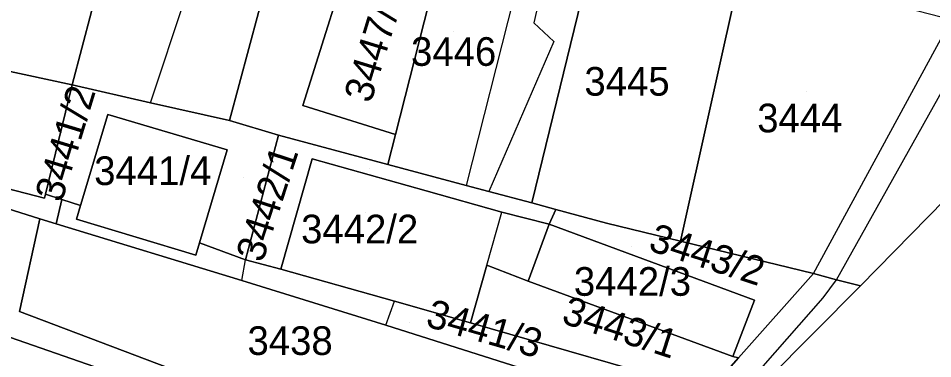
# Model space of a CAD drawing. Extents: x -262657 to -261595, y -1238015 to -1237156.
# Drawn here: x -262129.4 to -262065.5, y -1237560.4 to -1237536.7 of the extents above; entities that cross this region are included whole.
import ezdxf

# ---------------------------------------------------------------- set-up
doc = ezdxf.new("R2010")
doc.units = 0
for name, color, linetype in [('body_kn', 7, 'Continuous'), ('kladpar_druhypozemkov', 7, 'Continuous'), ('kladpar_hranice', 7, 'Continuous'), ('kladpar_parcelnecisla', 7, 'Continuous'), ('kladpar_plochy', 7, 'Continuous'), ('zappar_hrandruhpozemk', 7, 'Continuous')]:
    doc.layers.add(name, color=color, linetype=linetype)

msp = doc.modelspace()

# ---------------------------------------------------------------- linework, layer by layer
at = {"layer": 'body_kn'}
for p, q in [((-262093.38, -1237536.98), (-262093.38, -1237536.98)), ((-262091.97, -1237538.29), (-262091.97, -1237538.29)), ((-262125.61, -1237541.31), (-262125.61, -1237541.31)), ((-262120.15, -1237542.57), (-262120.15, -1237542.57)), ((-262120.15, -1237542.57), (-262120.15, -1237542.57)), ((-262109.51, -1237542.75), (-262109.51, -1237542.75)), ((-262123.13, -1237543.37), (-262123.13, -1237543.37)), ((-262114.63, -1237543.8), (-262114.63, -1237543.8)), ((-262103.04, -1237544.78), (-262103.04, -1237544.78)), ((-262111.21, -1237544.82), (-262111.21, -1237544.82)), ((-262111.21, -1237544.82), (-262111.21, -1237544.82)), ((-262114.78, -1237545.85), (-262114.78, -1237545.85)), ((-262108.85, -1237546.48), (-262108.85, -1237546.48)), ((-262108.85, -1237546.48), (-262108.85, -1237546.48)), ((-262103.57, -1237546.86), (-262103.57, -1237546.86)), ((-262098.1, -1237548.32), (-262098.1, -1237548.32)), ((-262127.54, -1237549.21), (-262127.54, -1237549.21)), ((-262127.48, -1237548.94), (-262127.48, -1237548.94)), ((-262100.9, -1237548.71), (-262100.9, -1237548.71)), ((-262096.53, -1237548.74), (-262096.53, -1237548.74)), ((-262126.34, -1237549.3), (-262126.34, -1237549.3)), ((-262126.34, -1237549.3), (-262126.34, -1237549.3)), ((-262125.02, -1237549.72), (-262125.02, -1237549.72)), ((-262093.52, -1237549.55), (-262093.52, -1237549.55)), ((-262095.62, -1237550.19), (-262095.62, -1237550.19)), ((-262091.83, -1237550.01), (-262091.83, -1237550.01)), ((-262127.87, -1237550.65), (-262127.87, -1237550.65)), ((-262126.73, -1237551), (-262126.73, -1237551)), ((-262125.3, -1237550.68), (-262125.3, -1237550.68)), ((-262092.31, -1237551.03), (-262092.31, -1237551.03)), ((-262092.31, -1237551.03), (-262092.31, -1237551.03)), ((-262088.3, -1237550.96), (-262088.3, -1237550.96)), ((-262116.73, -1237552.34), (-262116.73, -1237552.34)), ((-262116.73, -1237552.34), (-262116.73, -1237552.34)), ((-262083.14, -1237552.21), (-262083.14, -1237552.21)), ((-262116.98, -1237553.19), (-262116.98, -1237553.19)), ((-262113.51, -1237553.51), (-262113.51, -1237553.51)), ((-262111.05, -1237554.18), (-262111.05, -1237554.18)), ((-262096.65, -1237553.9), (-262096.65, -1237553.9)), ((-262096.65, -1237553.9), (-262096.65, -1237553.9)), ((-262113.76, -1237554.97), (-262113.76, -1237554.97)), ((-262113.76, -1237554.97), (-262113.76, -1237554.97)), ((-262073.85, -1237554.47), (-262073.85, -1237554.47)), ((-262073.85, -1237554.47), (-262073.85, -1237554.47)), ((-262072.25, -1237554.91), (-262072.25, -1237554.91)), ((-262072.25, -1237554.91), (-262072.25, -1237554.91)), ((-262093.78, -1237555), (-262093.78, -1237555)), ((-262070.57, -1237555.33), (-262070.57, -1237555.33)), ((-262073.17, -1237556.17), (-262073.17, -1237556.17)), ((-262103.11, -1237556.41), (-262103.11, -1237556.41)), ((-262077.98, -1237556.33), (-262077.98, -1237556.33)), ((-262129.29, -1237557.12), (-262129.29, -1237557.12)), ((-262103.7, -1237558.09), (-262103.7, -1237558.09)), ((-262103.7, -1237558.09), (-262103.7, -1237558.09)), ((-262097.79, -1237557.91), (-262097.79, -1237557.91)), ((-262079.48, -1237560.26), (-262079.48, -1237560.26)), ((-262079.08, -1237560.37), (-262079.08, -1237560.37))]:
    msp.add_line(p, q, dxfattribs=at)
at = {"layer": 'kladpar_druhypozemkov'}
for p, q in [((-262105.16, -1237537.41), (-262105.16, -1237537.41)), ((-262098.96, -1237537.61), (-262098.96, -1237537.61)), ((-262086.35, -1237540.32), (-262086.35, -1237540.32)), ((-262074.34, -1237541.74), (-262074.34, -1237541.74)), ((-262119.98, -1237546.04), (-262119.98, -1237546.04)), ((-262104.85, -1237547.16), (-262104.85, -1237547.16)), ((-262113.66, -1237547.78), (-262113.66, -1237547.78)), ((-262105.1, -1237550.25), (-262105.1, -1237550.25)), ((-262086.56, -1237552.58), (-262086.56, -1237552.58)), ((-262086.53, -1237554.49), (-262086.53, -1237554.49)), ((-262110.69, -1237558.11), (-262110.69, -1237558.11)), ((-262102.08, -1237557.92), (-262102.08, -1237557.92)), ((-262093.17, -1237558.06), (-262093.17, -1237558.06))]:
    msp.add_line(p, q, dxfattribs=at)
at = {"layer": 'kladpar_hranice'}
for points in [[(-262120.57, -1237522.58), (-262124.27, -1237536.19), (-262125.61, -1237541.31), (-262135.69, -1237539.13), (-262131.12, -1237519.93), (-262120.57, -1237522.58)], [(-262120.57, -1237522.58), (-262114.11, -1237524.36), (-262112.64, -1237524.8), (-262109.74, -1237525.5), (-262111.25, -1237531.21), (-262114.63, -1237543.8), (-262120.15, -1237542.57), (-262125.61, -1237541.31), (-262124.27, -1237536.19), (-262120.57, -1237522.58)], [(-262109.74, -1237525.5), (-262098.86, -1237527.8), (-262099.87, -1237532.22), (-262105.62, -1237530.39), (-262109.51, -1237542.75), (-262103.04, -1237544.78), (-262103.57, -1237546.86), (-262111.21, -1237544.82), (-262114.63, -1237543.8), (-262111.25, -1237531.21), (-262109.74, -1237525.5)], [(-262098.86, -1237527.8), (-262094.29, -1237528.94), (-262092.23, -1237529.48), (-262088.85, -1237530.38), (-262093.52, -1237549.55), (-262096.53, -1237548.74), (-262098.1, -1237548.32), (-262103.57, -1237546.86), (-262103.04, -1237544.78), (-262100.04, -1237532.96), (-262099.87, -1237532.22), (-262098.86, -1237527.8)], [(-262099.87, -1237532.22), (-262100.04, -1237532.96), (-262103.04, -1237544.78), (-262109.51, -1237542.75), (-262105.62, -1237530.39), (-262099.87, -1237532.22)], [(-262088.85, -1237530.38), (-262078.85, -1237532.95), (-262083.14, -1237552.21), (-262088.3, -1237550.96), (-262091.83, -1237550.01), (-262093.52, -1237549.55), (-262088.85, -1237530.38)], [(-262078.85, -1237532.95), (-262064.22, -1237536.75), (-262062.54, -1237537.56), (-262058.8, -1237539.3), (-262057.6, -1237542.11), (-262070.57, -1237555.33), (-262072.25, -1237554.91), (-262073.85, -1237554.47), (-262083.14, -1237552.21), (-262078.85, -1237532.95)], [(-262126.34, -1237549.3), (-262126.73, -1237551), (-262127.87, -1237550.65), (-262146.14, -1237544.88), (-262154.15, -1237542.73), (-262161.8, -1237540.63), (-262157.47, -1237540.31), (-262157.42, -1237538.21), (-262146.02, -1237536.76), (-262147.78, -1237543.97), (-262127.54, -1237549.21), (-262127.48, -1237548.94), (-262126.34, -1237549.3)], [(-262146.02, -1237536.76), (-262143.66, -1237537.3), (-262135.69, -1237539.13), (-262125.61, -1237541.31), (-262127.48, -1237548.94), (-262127.54, -1237549.21), (-262147.78, -1237543.97), (-262146.02, -1237536.76)], [(-262113.92, -1237604.85), (-262120, -1237601.39), (-262121.24, -1237601.28), (-262122.86, -1237600.4), (-262122.24, -1237599.28), (-262120.21, -1237600.52), (-262113.99, -1237594.34), (-262109.31, -1237589.66), (-262106.11, -1237586.39), (-262098.57, -1237579.94), (-262091.36, -1237573.71), (-262089.88, -1237572.05), (-262085.88, -1237567.52), (-262083.16, -1237564.51), (-262081.16, -1237562.71), (-262079.08, -1237560.37), (-262073.85, -1237554.47), (-262072.25, -1237554.91), (-262070.57, -1237555.33), (-262057.6, -1237542.11), (-262058.8, -1237539.3)], [(-262111.21, -1237544.82), (-262113.51, -1237553.51), (-262116.73, -1237552.34), (-262114.78, -1237545.85), (-262123.13, -1237543.37), (-262125.02, -1237549.72), (-262126.34, -1237549.3), (-262127.48, -1237548.94), (-262125.61, -1237541.31), (-262120.15, -1237542.57), (-262114.63, -1237543.8), (-262111.21, -1237544.82)], [(-262150.98, -1237551.9), (-262162.52, -1237548.12), (-262159.92, -1237548.65), (-262159.39, -1237546.68), (-262155.46, -1237547.69), (-262154.15, -1237542.73), (-262146.14, -1237544.88), (-262127.87, -1237550.65), (-262129.29, -1237557.12), (-262089.88, -1237572.05), (-262091.36, -1237573.71), (-262114.93, -1237564.15), (-262131.62, -1237558.35), (-262139.63, -1237555.56), (-262146.25, -1237553.37), (-262150.98, -1237551.9)], [(-262116.73, -1237552.34), (-262116.98, -1237553.19), (-262125.3, -1237550.68), (-262125.02, -1237549.72), (-262123.13, -1237543.37), (-262114.78, -1237545.85), (-262116.73, -1237552.34)], [(-262111.21, -1237544.82), (-262103.57, -1237546.86), (-262098.1, -1237548.32), (-262096.53, -1237548.74), (-262093.52, -1237549.55), (-262091.83, -1237550.01), (-262092.31, -1237551.03), (-262095.62, -1237550.19), (-262100.9, -1237548.71), (-262108.85, -1237546.48), (-262111.05, -1237554.18), (-262113.51, -1237553.51), (-262111.21, -1237544.82)], [(-262108.85, -1237546.48), (-262100.9, -1237548.71), (-262095.62, -1237550.19), (-262092.31, -1237551.03), (-262093.78, -1237555), (-262096.65, -1237553.9), (-262097.79, -1237557.91), (-262103.11, -1237556.41), (-262111.05, -1237554.18), (-262108.85, -1237546.48)], [(-262081.16, -1237562.71), (-262083.16, -1237564.51), (-262088, -1237563.03), (-262094.39, -1237561.04), (-262103.7, -1237558.09), (-262113.76, -1237554.97), (-262126.73, -1237551), (-262126.34, -1237549.3), (-262125.02, -1237549.72), (-262125.3, -1237550.68), (-262116.98, -1237553.19), (-262116.73, -1237552.34), (-262113.51, -1237553.51), (-262111.05, -1237554.18), (-262103.11, -1237556.41), (-262097.79, -1237557.91), (-262081.16, -1237562.71)], [(-262092.31, -1237551.03), (-262091.83, -1237550.01), (-262088.3, -1237550.96), (-262083.14, -1237552.21), (-262073.85, -1237554.47), (-262079.08, -1237560.37), (-262079.48, -1237560.26), (-262077.98, -1237556.33), (-262092.31, -1237551.03)], [(-262085.88, -1237567.52), (-262089.88, -1237572.05), (-262129.29, -1237557.12), (-262127.87, -1237550.65), (-262126.73, -1237551), (-262113.76, -1237554.97), (-262103.7, -1237558.09), (-262094.39, -1237561.04), (-262095.33, -1237564.81), (-262088.92, -1237566.62), (-262085.88, -1237567.52)], [(-262092.31, -1237551.03), (-262077.98, -1237556.33), (-262079.48, -1237560.26), (-262093.78, -1237555), (-262092.31, -1237551.03)], [(-262081.16, -1237562.71), (-262097.79, -1237557.91), (-262096.65, -1237553.9), (-262093.78, -1237555), (-262079.48, -1237560.26), (-262079.08, -1237560.37), (-262081.16, -1237562.71)], [(-262134.31, -1237565.86), (-262131.62, -1237558.35), (-262114.93, -1237564.15), (-262115.04, -1237564.59), (-262116.45, -1237568.87), (-262117.56, -1237572.44), (-262118.76, -1237571.97), (-262119.92, -1237571.51), (-262129.38, -1237567.76), (-262133.96, -1237565.99), (-262134.31, -1237565.86)]]:
    msp.add_lwpolyline(points, dxfattribs=at)
at = {"layer": 'kladpar_plochy'}
for points in [[(-262120.57, -1237522.58), (-262124.27, -1237536.19), (-262125.61, -1237541.31), (-262135.69, -1237539.13), (-262131.12, -1237519.93)], [(-262120.57, -1237522.58), (-262114.11, -1237524.36), (-262112.64, -1237524.8), (-262109.74, -1237525.5), (-262111.25, -1237531.21), (-262114.63, -1237543.8), (-262120.15, -1237542.57), (-262125.61, -1237541.31), (-262124.27, -1237536.19)], [(-262109.74, -1237525.5), (-262098.86, -1237527.8), (-262099.87, -1237532.22), (-262105.62, -1237530.39), (-262109.51, -1237542.75), (-262103.04, -1237544.78), (-262103.57, -1237546.86), (-262111.21, -1237544.82), (-262114.63, -1237543.8), (-262111.25, -1237531.21)], [(-262098.86, -1237527.8), (-262094.29, -1237528.94), (-262092.23, -1237529.48), (-262088.85, -1237530.38), (-262093.52, -1237549.55), (-262096.53, -1237548.74), (-262098.1, -1237548.32), (-262103.57, -1237546.86), (-262103.04, -1237544.78), (-262100.04, -1237532.96), (-262099.87, -1237532.22)], [(-262099.87, -1237532.22), (-262100.04, -1237532.96), (-262103.04, -1237544.78), (-262109.51, -1237542.75), (-262105.62, -1237530.39)], [(-262088.85, -1237530.38), (-262078.85, -1237532.95), (-262083.14, -1237552.21), (-262088.3, -1237550.96), (-262091.83, -1237550.01), (-262093.52, -1237549.55)], [(-262078.85, -1237532.95), (-262064.22, -1237536.75), (-262062.54, -1237537.56), (-262058.8, -1237539.3), (-262057.6, -1237542.11), (-262070.57, -1237555.33), (-262072.25, -1237554.91), (-262073.85, -1237554.47), (-262083.14, -1237552.21)], [(-262126.34, -1237549.3), (-262126.73, -1237551), (-262127.87, -1237550.65), (-262146.14, -1237544.88), (-262154.15, -1237542.73), (-262161.8, -1237540.63), (-262157.47, -1237540.31), (-262157.42, -1237538.21), (-262146.02, -1237536.76), (-262147.78, -1237543.97), (-262127.54, -1237549.21), (-262127.48, -1237548.94)], [(-262146.02, -1237536.76), (-262143.66, -1237537.3), (-262135.69, -1237539.13), (-262125.61, -1237541.31), (-262127.48, -1237548.94), (-262127.54, -1237549.21), (-262147.78, -1237543.97)], [(-262111.21, -1237544.82), (-262113.51, -1237553.51), (-262116.73, -1237552.34), (-262114.78, -1237545.85), (-262123.13, -1237543.37), (-262125.02, -1237549.72), (-262126.34, -1237549.3), (-262127.48, -1237548.94), (-262125.61, -1237541.31), (-262120.15, -1237542.57), (-262114.63, -1237543.8)], [(-262150.98, -1237551.9), (-262162.52, -1237548.12), (-262159.92, -1237548.65), (-262159.39, -1237546.68), (-262155.46, -1237547.69), (-262154.15, -1237542.73), (-262146.14, -1237544.88), (-262127.87, -1237550.65), (-262129.29, -1237557.12), (-262089.88, -1237572.05), (-262091.36, -1237573.71), (-262114.93, -1237564.15), (-262131.62, -1237558.35), (-262139.63, -1237555.56), (-262146.25, -1237553.37)], [(-262116.73, -1237552.34), (-262116.98, -1237553.19), (-262125.3, -1237550.68), (-262125.02, -1237549.72), (-262123.13, -1237543.37), (-262114.78, -1237545.85)], [(-262111.21, -1237544.82), (-262103.57, -1237546.86), (-262098.1, -1237548.32), (-262096.53, -1237548.74), (-262093.52, -1237549.55), (-262091.83, -1237550.01), (-262092.31, -1237551.03), (-262095.62, -1237550.19), (-262100.9, -1237548.71), (-262108.85, -1237546.48), (-262111.05, -1237554.18), (-262113.51, -1237553.51)], [(-262108.85, -1237546.48), (-262100.9, -1237548.71), (-262095.62, -1237550.19), (-262092.31, -1237551.03), (-262093.78, -1237555), (-262096.65, -1237553.9), (-262097.79, -1237557.91), (-262103.11, -1237556.41), (-262111.05, -1237554.18)], [(-262081.16, -1237562.71), (-262083.16, -1237564.51), (-262088, -1237563.03), (-262094.39, -1237561.04), (-262103.7, -1237558.09), (-262113.76, -1237554.97), (-262126.73, -1237551), (-262126.34, -1237549.3), (-262125.02, -1237549.72), (-262125.3, -1237550.68), (-262116.98, -1237553.19), (-262116.73, -1237552.34), (-262113.51, -1237553.51), (-262111.05, -1237554.18), (-262103.11, -1237556.41), (-262097.79, -1237557.91)], [(-262092.31, -1237551.03), (-262091.83, -1237550.01), (-262088.3, -1237550.96), (-262083.14, -1237552.21), (-262073.85, -1237554.47), (-262079.08, -1237560.37), (-262079.48, -1237560.26), (-262077.98, -1237556.33)], [(-262085.88, -1237567.52), (-262089.88, -1237572.05), (-262129.29, -1237557.12), (-262127.87, -1237550.65), (-262126.73, -1237551), (-262113.76, -1237554.97), (-262103.7, -1237558.09), (-262094.39, -1237561.04), (-262095.33, -1237564.81), (-262088.92, -1237566.62)], [(-262092.31, -1237551.03), (-262077.98, -1237556.33), (-262079.48, -1237560.26), (-262093.78, -1237555)], [(-262081.16, -1237562.71), (-262097.79, -1237557.91), (-262096.65, -1237553.9), (-262093.78, -1237555), (-262079.48, -1237560.26), (-262079.08, -1237560.37)], [(-262134.31, -1237565.86), (-262131.62, -1237558.35), (-262114.93, -1237564.15), (-262115.04, -1237564.59), (-262116.45, -1237568.87), (-262117.56, -1237572.44), (-262118.76, -1237571.97), (-262119.92, -1237571.51), (-262129.38, -1237567.76), (-262133.96, -1237565.99)]]:
    msp.add_lwpolyline(points, close=True, dxfattribs=at)
msp.add_lwpolyline([(-262113.92, -1237604.85), (-262120, -1237601.39), (-262121.24, -1237601.28), (-262122.86, -1237600.4), (-262122.24, -1237599.28), (-262120.21, -1237600.52), (-262113.99, -1237594.34), (-262109.31, -1237589.66), (-262106.11, -1237586.39), (-262098.57, -1237579.94), (-262091.36, -1237573.71), (-262089.88, -1237572.05), (-262085.88, -1237567.52), (-262083.16, -1237564.51), (-262081.16, -1237562.71), (-262079.08, -1237560.37), (-262073.85, -1237554.47), (-262072.25, -1237554.91), (-262070.57, -1237555.33), (-262057.6, -1237542.11)], dxfattribs=at)
at = {"layer": 'zappar_hrandruhpozemk'}
for p, q in [((-262120.15, -1237542.57), (-262114.11, -1237524.36)), ((-262094.5, -1237534.16), (-262098.1, -1237548.32)), ((-262073.85, -1237554.47), (-262064.22, -1237536.75)), ((-262072.25, -1237554.91), (-262062.54, -1237537.56)), ((-262091.97, -1237538.29), (-262096.53, -1237548.74)), ((-262096.65, -1237553.9), (-262095.62, -1237550.19)), ((-262113.76, -1237554.97), (-262113.51, -1237553.51)), ((-262073.17, -1237556.17), (-262072.25, -1237554.91)), ((-262087.17, -1237572.05), (-262070.57, -1237555.33)), ((-262087.17, -1237572.05), (-262073.17, -1237556.17)), ((-262103.7, -1237558.09), (-262103.11, -1237556.41))]:
    msp.add_line(p, q, dxfattribs=at)
msp.add_lwpolyline([(-262092.23, -1237529.48), (-262093.09, -1237532.26), (-262092.51, -1237533.18), (-262093.38, -1237536.98), (-262091.97, -1237538.29)], dxfattribs=at)

# ---------------------------------------------------------------- texts
at = {"layer": 'kladpar_parcelnecisla'}
for s, rotation, p in [('3447/2', 73, (-262104.763, -1237542.656)), ('3441/2', 73, (-262126.337, -1237549.58)), ('3442/1', 72, (-262112.32, -1237553.782)), ('3443/2', 342, (-262085.459, -1237552.832)), ('3443/1', 342, (-262091.527, -1237557.906)), ('3441/3', 344, (-262101.011, -1237558.141))]:
    msp.add_text(s, height=2, rotation=rotation, dxfattribs=at).set_placement(p)
for s, p in [('3446', (-262101.952, -1237539.98)), ('3445', (-262089.847, -1237542.06)), ('3444', (-262077.782, -1237544.62)), ('3441/4', (-262124.073, -1237548.3)), ('3442/2', (-262109.626, -1237552.37)), ('3442/3', (-262090.581, -1237556.03)), ('3438', (-262113.368, -1237560.16))]:
    msp.add_text(s, height=2, dxfattribs=at).set_placement(p)

doc.saveas('drawing.dxf')
